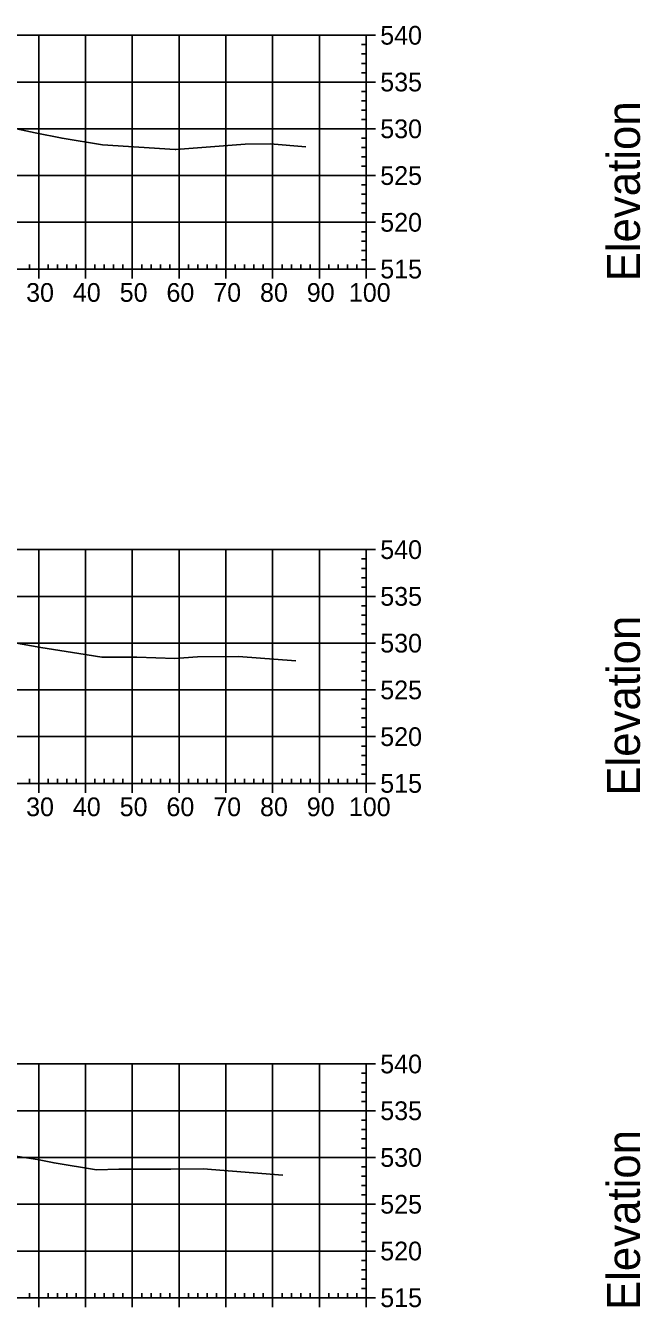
# Model space of a CAD drawing. Extents: x 708103 to 717568, y 374476 to 378707.
# Drawn here: x 716383.7 to 716515.1, y 377226 to 377500.1 of the extents above; entities that cross this region are included whole.
import ezdxf

# ---------------------------------------------------------------- set-up
doc = ezdxf.new("R2010")
doc.units = 0
for name, color, linetype in [('57', 7, 'Continuous'), ('60', 7, 'Continuous'), ('Existing', 7, 'Continuous')]:
    doc.layers.add(name, color=color, linetype=linetype)

msp = doc.modelspace()

# ---------------------------------------------------------------- linework, layer by layer
at = {"layer": '57'}
for p, q in [((716256.5, 377498.07), (716456.5, 377498.07)), ((716386.5, 377448.07), (716386.5, 377498.07)), ((716396.5, 377448.07), (716396.5, 377498.07)), ((716406.5, 377448.07), (716406.5, 377498.07)), ((716416.5, 377448.07), (716416.5, 377498.07)), ((716426.5, 377448.07), (716426.5, 377498.07)), ((716436.5, 377448.07), (716436.5, 377498.07)), ((716446.5, 377448.07), (716446.5, 377498.07)), ((716456.5, 377448.07), (716456.5, 377498.07)), ((716456.5, 377448.07), (716456.5, 377498.07)), ((716458.5, 377498.07), (716456.5, 377498.07)), ((716456.5, 377496.07), (716455.5, 377496.07)), ((716456.5, 377494.07), (716455.5, 377494.07)), ((716456.5, 377492.07), (716455.5, 377492.07)), ((716456.5, 377490.07), (716455.5, 377490.07)), ((716256.5, 377488.07), (716456.5, 377488.07)), ((716456.5, 377486.07), (716455.5, 377486.07)), ((716458.5, 377488.07), (716456.5, 377488.07)), ((716456.5, 377484.07), (716455.5, 377484.07)), ((716456.5, 377482.07), (716455.5, 377482.07)), ((716256.5, 377478.07), (716456.5, 377478.07)), ((716456.5, 377480.07), (716455.5, 377480.07)), ((716458.5, 377478.07), (716456.5, 377478.07)), ((716456.5, 377476.07), (716455.5, 377476.07)), ((716456.5, 377474.07), (716455.5, 377474.07)), ((716456.5, 377472.07), (716455.5, 377472.07)), ((716456.5, 377470.07), (716455.5, 377470.07)), ((716256.5, 377468.07), (716456.5, 377468.07)), ((716458.5, 377468.07), (716456.5, 377468.07)), ((716456.5, 377466.07), (716455.5, 377466.07)), ((716456.5, 377464.07), (716455.5, 377464.07)), ((716456.5, 377462.07), (716455.5, 377462.07)), ((716456.5, 377460.07), (716455.5, 377460.07)), ((716256.5, 377458.07), (716456.5, 377458.07)), ((716456.5, 377456.07), (716455.5, 377456.07)), ((716458.5, 377458.07), (716456.5, 377458.07)), ((716456.5, 377454.07), (716455.5, 377454.07)), ((716456.5, 377452.07), (716455.5, 377452.07)), ((716456.5, 377450.07), (716455.5, 377450.07)), ((716256.5, 377448.07), (716456.5, 377448.07)), ((716256.5, 377448.07), (716456.5, 377448.07)), ((716384.5, 377448.07), (716384.5, 377449.07)), ((716386.5, 377446.07), (716386.5, 377448.07)), ((716388.5, 377448.07), (716388.5, 377449.07)), ((716390.5, 377448.07), (716390.5, 377449.07)), ((716392.5, 377448.07), (716392.5, 377449.07)), ((716394.5, 377448.07), (716394.5, 377449.07)), ((716396.5, 377446.07), (716396.5, 377448.07)), ((716398.5, 377448.07), (716398.5, 377449.07)), ((716400.5, 377448.07), (716400.5, 377449.07)), ((716402.5, 377448.07), (716402.5, 377449.07)), ((716404.5, 377448.07), (716404.5, 377449.07)), ((716406.5, 377446.07), (716406.5, 377448.07)), ((716408.5, 377448.07), (716408.5, 377449.07)), ((716410.5, 377448.07), (716410.5, 377449.07)), ((716412.5, 377448.07), (716412.5, 377449.07)), ((716414.5, 377448.07), (716414.5, 377449.07)), ((716416.5, 377446.07), (716416.5, 377448.07)), ((716418.5, 377448.07), (716418.5, 377449.07)), ((716420.5, 377448.07), (716420.5, 377449.07)), ((716422.5, 377448.07), (716422.5, 377449.07)), ((716424.5, 377448.07), (716424.5, 377449.07)), ((716426.5, 377446.07), (716426.5, 377448.07)), ((716428.5, 377448.07), (716428.5, 377449.07)), ((716430.5, 377448.07), (716430.5, 377449.07)), ((716432.5, 377448.07), (716432.5, 377449.07)), ((716434.5, 377448.07), (716434.5, 377449.07)), ((716436.5, 377446.07), (716436.5, 377448.07)), ((716438.5, 377448.07), (716438.5, 377449.07)), ((716440.5, 377448.07), (716440.5, 377449.07)), ((716442.5, 377448.07), (716442.5, 377449.07)), ((716444.5, 377448.07), (716444.5, 377449.07)), ((716446.5, 377446.07), (716446.5, 377448.07)), ((716448.5, 377448.07), (716448.5, 377449.07)), ((716450.5, 377448.07), (716450.5, 377449.07)), ((716452.5, 377448.07), (716452.5, 377449.07)), ((716454.5, 377448.07), (716454.5, 377449.07)), ((716456.5, 377446.07), (716456.5, 377448.07)), ((716458.5, 377448.07), (716456.5, 377448.07)), ((716256.5, 377388.07), (716456.5, 377388.07)), ((716386.5, 377338.07), (716386.5, 377388.07)), ((716396.5, 377338.07), (716396.5, 377388.07)), ((716406.5, 377338.07), (716406.5, 377388.07)), ((716416.5, 377338.07), (716416.5, 377388.07)), ((716426.5, 377338.07), (716426.5, 377388.07)), ((716436.5, 377338.07), (716436.5, 377388.07)), ((716446.5, 377338.07), (716446.5, 377388.07)), ((716456.5, 377338.07), (716456.5, 377388.07)), ((716456.5, 377338.07), (716456.5, 377388.07)), ((716458.5, 377388.07), (716456.5, 377388.07)), ((716456.5, 377386.07), (716455.5, 377386.07)), ((716456.5, 377384.07), (716455.5, 377384.07)), ((716456.5, 377382.07), (716455.5, 377382.07)), ((716456.5, 377380.07), (716455.5, 377380.07)), ((716256.5, 377378.07), (716456.5, 377378.07)), ((716456.5, 377376.07), (716455.5, 377376.07)), ((716458.5, 377378.07), (716456.5, 377378.07)), ((716456.5, 377374.07), (716455.5, 377374.07)), ((716456.5, 377372.07), (716455.5, 377372.07)), ((716256.5, 377368.07), (716456.5, 377368.07)), ((716456.5, 377370.07), (716455.5, 377370.07)), ((716458.5, 377368.07), (716456.5, 377368.07)), ((716456.5, 377366.07), (716455.5, 377366.07)), ((716456.5, 377364.07), (716455.5, 377364.07)), ((716456.5, 377362.07), (716455.5, 377362.07)), ((716456.5, 377360.07), (716455.5, 377360.07)), ((716256.5, 377358.07), (716456.5, 377358.07)), ((716458.5, 377358.07), (716456.5, 377358.07)), ((716456.5, 377356.07), (716455.5, 377356.07)), ((716456.5, 377354.07), (716455.5, 377354.07)), ((716456.5, 377352.07), (716455.5, 377352.07)), ((716456.5, 377350.07), (716455.5, 377350.07)), ((716256.5, 377348.07), (716456.5, 377348.07)), ((716456.5, 377346.07), (716455.5, 377346.07)), ((716458.5, 377348.07), (716456.5, 377348.07)), ((716456.5, 377344.07), (716455.5, 377344.07)), ((716456.5, 377342.07), (716455.5, 377342.07)), ((716256.5, 377338.07), (716456.5, 377338.07)), ((716256.5, 377338.07), (716456.5, 377338.07)), ((716384.5, 377338.07), (716384.5, 377339.07)), ((716386.5, 377336.07), (716386.5, 377338.07)), ((716388.5, 377338.07), (716388.5, 377339.07)), ((716390.5, 377338.07), (716390.5, 377339.07)), ((716392.5, 377338.07), (716392.5, 377339.07)), ((716394.5, 377338.07), (716394.5, 377339.07)), ((716396.5, 377336.07), (716396.5, 377338.07)), ((716398.5, 377338.07), (716398.5, 377339.07)), ((716400.5, 377338.07), (716400.5, 377339.07)), ((716402.5, 377338.07), (716402.5, 377339.07)), ((716404.5, 377338.07), (716404.5, 377339.07)), ((716406.5, 377336.07), (716406.5, 377338.07)), ((716408.5, 377338.07), (716408.5, 377339.07)), ((716410.5, 377338.07), (716410.5, 377339.07)), ((716412.5, 377338.07), (716412.5, 377339.07)), ((716414.5, 377338.07), (716414.5, 377339.07)), ((716416.5, 377336.07), (716416.5, 377338.07)), ((716418.5, 377338.07), (716418.5, 377339.07)), ((716420.5, 377338.07), (716420.5, 377339.07)), ((716422.5, 377338.07), (716422.5, 377339.07)), ((716424.5, 377338.07), (716424.5, 377339.07)), ((716426.5, 377336.07), (716426.5, 377338.07)), ((716428.5, 377338.07), (716428.5, 377339.07)), ((716430.5, 377338.07), (716430.5, 377339.07)), ((716432.5, 377338.07), (716432.5, 377339.07)), ((716434.5, 377338.07), (716434.5, 377339.07)), ((716436.5, 377336.07), (716436.5, 377338.07)), ((716438.5, 377338.07), (716438.5, 377339.07)), ((716440.5, 377338.07), (716440.5, 377339.07)), ((716442.5, 377338.07), (716442.5, 377339.07)), ((716444.5, 377338.07), (716444.5, 377339.07)), ((716446.5, 377336.07), (716446.5, 377338.07)), ((716448.5, 377338.07), (716448.5, 377339.07)), ((716450.5, 377338.07), (716450.5, 377339.07)), ((716452.5, 377338.07), (716452.5, 377339.07)), ((716454.5, 377338.07), (716454.5, 377339.07)), ((716456.5, 377340.07), (716455.5, 377340.07)), ((716456.5, 377336.07), (716456.5, 377338.07)), ((716458.5, 377338.07), (716456.5, 377338.07)), ((716256.5, 377278.07), (716456.5, 377278.07)), ((716386.5, 377228.07), (716386.5, 377278.07)), ((716396.5, 377228.07), (716396.5, 377278.07)), ((716406.5, 377228.07), (716406.5, 377278.07)), ((716416.5, 377228.07), (716416.5, 377278.07)), ((716426.5, 377228.07), (716426.5, 377278.07)), ((716436.5, 377228.07), (716436.5, 377278.07)), ((716446.5, 377228.07), (716446.5, 377278.07)), ((716456.5, 377228.07), (716456.5, 377278.07)), ((716456.5, 377228.07), (716456.5, 377278.07)), ((716458.5, 377278.07), (716456.5, 377278.07)), ((716456.5, 377276.07), (716455.5, 377276.07)), ((716456.5, 377274.07), (716455.5, 377274.07)), ((716456.5, 377272.07), (716455.5, 377272.07)), ((716456.5, 377270.07), (716455.5, 377270.07)), ((716256.5, 377268.07), (716456.5, 377268.07)), ((716458.5, 377268.07), (716456.5, 377268.07)), ((716456.5, 377266.07), (716455.5, 377266.07)), ((716456.5, 377264.07), (716455.5, 377264.07)), ((716456.5, 377262.07), (716455.5, 377262.07)), ((716456.5, 377260.07), (716455.5, 377260.07)), ((716256.5, 377258.07), (716456.5, 377258.07)), ((716456.5, 377256.07), (716455.5, 377256.07)), ((716458.5, 377258.07), (716456.5, 377258.07)), ((716456.5, 377254.07), (716455.5, 377254.07)), ((716456.5, 377252.07), (716455.5, 377252.07)), ((716456.5, 377250.07), (716455.5, 377250.07)), ((716256.5, 377248.07), (716456.5, 377248.07)), ((716458.5, 377248.07), (716456.5, 377248.07)), ((716456.5, 377246.07), (716455.5, 377246.07)), ((716456.5, 377244.07), (716455.5, 377244.07)), ((716456.5, 377242.07), (716455.5, 377242.07)), ((716456.5, 377240.07), (716455.5, 377240.07)), ((716256.5, 377238.07), (716456.5, 377238.07)), ((716458.5, 377238.07), (716456.5, 377238.07)), ((716456.5, 377236.07), (716455.5, 377236.07)), ((716456.5, 377234.07), (716455.5, 377234.07)), ((716456.5, 377232.07), (716455.5, 377232.07)), ((716256.5, 377228.07), (716456.5, 377228.07)), ((716256.5, 377228.07), (716456.5, 377228.07)), ((716384.5, 377228.07), (716384.5, 377229.07)), ((716386.5, 377226.07), (716386.5, 377228.07)), ((716388.5, 377228.07), (716388.5, 377229.07)), ((716390.5, 377228.07), (716390.5, 377229.07)), ((716392.5, 377228.07), (716392.5, 377229.07)), ((716394.5, 377228.07), (716394.5, 377229.07)), ((716396.5, 377226.07), (716396.5, 377228.07)), ((716398.5, 377228.07), (716398.5, 377229.07)), ((716400.5, 377228.07), (716400.5, 377229.07)), ((716402.5, 377228.07), (716402.5, 377229.07)), ((716404.5, 377228.07), (716404.5, 377229.07)), ((716406.5, 377226.07), (716406.5, 377228.07)), ((716408.5, 377228.07), (716408.5, 377229.07)), ((716410.5, 377228.07), (716410.5, 377229.07)), ((716412.5, 377228.07), (716412.5, 377229.07)), ((716414.5, 377228.07), (716414.5, 377229.07)), ((716416.5, 377226.07), (716416.5, 377228.07)), ((716418.5, 377228.07), (716418.5, 377229.07)), ((716420.5, 377228.07), (716420.5, 377229.07)), ((716422.5, 377228.07), (716422.5, 377229.07)), ((716424.5, 377228.07), (716424.5, 377229.07)), ((716426.5, 377226.07), (716426.5, 377228.07)), ((716428.5, 377228.07), (716428.5, 377229.07)), ((716430.5, 377228.07), (716430.5, 377229.07)), ((716432.5, 377228.07), (716432.5, 377229.07)), ((716434.5, 377228.07), (716434.5, 377229.07)), ((716436.5, 377226.07), (716436.5, 377228.07)), ((716438.5, 377228.07), (716438.5, 377229.07)), ((716440.5, 377228.07), (716440.5, 377229.07)), ((716442.5, 377228.07), (716442.5, 377229.07)), ((716444.5, 377228.07), (716444.5, 377229.07)), ((716446.5, 377226.07), (716446.5, 377228.07)), ((716448.5, 377228.07), (716448.5, 377229.07)), ((716450.5, 377228.07), (716450.5, 377229.07)), ((716452.5, 377228.07), (716452.5, 377229.07)), ((716454.5, 377228.07), (716454.5, 377229.07)), ((716456.5, 377230.07), (716455.5, 377230.07)), ((716456.5, 377226.07), (716456.5, 377228.07)), ((716458.5, 377228.07), (716456.5, 377228.07))]:
    msp.add_line(p, q, dxfattribs=at)
at = {"layer": 'Existing'}
for points in [[(716375.3, 377479.44), (716385.75, 377477.19), (716391.47, 377476.05), (716400.11, 377474.66), (716415.66, 377473.61), (716415.73, 377473.61), (716415.8, 377473.61), (716430.59, 377474.78), (716436, 377474.85), (716443.61, 377474.23)], [(716376.1, 377369.07), (716386.97, 377367.16), (716395.07, 377365.85), (716400.01, 377365.05), (716407.46, 377365.08), (716415.56, 377364.77), (716420.43, 377365.15), (716429.23, 377365.25), (716441.48, 377364.27)], [(716275.44, 377260.52), (716277.32, 377260.38), (716287.25, 377259.74), (716305.42, 377259.55), (716316.04, 377260.08), (716325.25, 377260.66), (716335.78, 377261.33), (716346.13, 377261.98), (716349.23, 377261.7), (716355.84, 377261.12), (716361.45, 377260.69), (716370.74, 377260.07), (716372.89, 377259.61), (716376.43, 377259.12), (716386.21, 377257.61), (716389.78, 377256.9), (716398.87, 377255.43), (716403.64, 377255.55), (716414.75, 377255.59), (716421.66, 377255.67), (716438.67, 377254.3)]]:
    msp.add_lwpolyline(points, dxfattribs=at)

# ---------------------------------------------------------------- texts
at = {"layer": '57'}
for s, p in [('540', (716459.5, 377496.07)), ('535', (716459.5, 377486.07)), ('530', (716459.5, 377476.07)), ('525', (716459.5, 377466.07)), ('520', (716459.5, 377456.07)), ('515', (716459.5, 377446.07)), ('30', (716383.8, 377441.07)), ('40', (716393.8, 377441.07)), ('50', (716403.8, 377441.07)), ('60', (716413.8, 377441.07)), ('70', (716423.8, 377441.07)), ('80', (716433.8, 377441.07)), ('90', (716443.8, 377441.07)), ('100', (716452.8, 377441.07)), ('540', (716459.5, 377386.07)), ('535', (716459.5, 377376.07)), ('530', (716459.5, 377366.07)), ('525', (716459.5, 377356.07)), ('520', (716459.5, 377346.07)), ('515', (716459.5, 377336.07)), ('30', (716383.8, 377331.07)), ('40', (716393.8, 377331.07)), ('50', (716403.8, 377331.07)), ('60', (716413.8, 377331.07)), ('70', (716423.8, 377331.07)), ('80', (716433.8, 377331.07)), ('90', (716443.8, 377331.07)), ('100', (716452.8, 377331.07)), ('540', (716459.5, 377276.07)), ('535', (716459.5, 377266.07)), ('530', (716459.5, 377256.07)), ('525', (716459.5, 377246.07)), ('520', (716459.5, 377236.07)), ('515', (716459.5, 377226.07))]:
    msp.add_text(s, height=4, dxfattribs=at).set_placement(p)
at = {"layer": '60'}
for p in [(716515, 377445.44), (716515, 377335.44), (716515, 377225.44)]:
    msp.add_text('Elevation', height=7, rotation=90, dxfattribs=at).set_placement(p)

doc.saveas('drawing.dxf')
